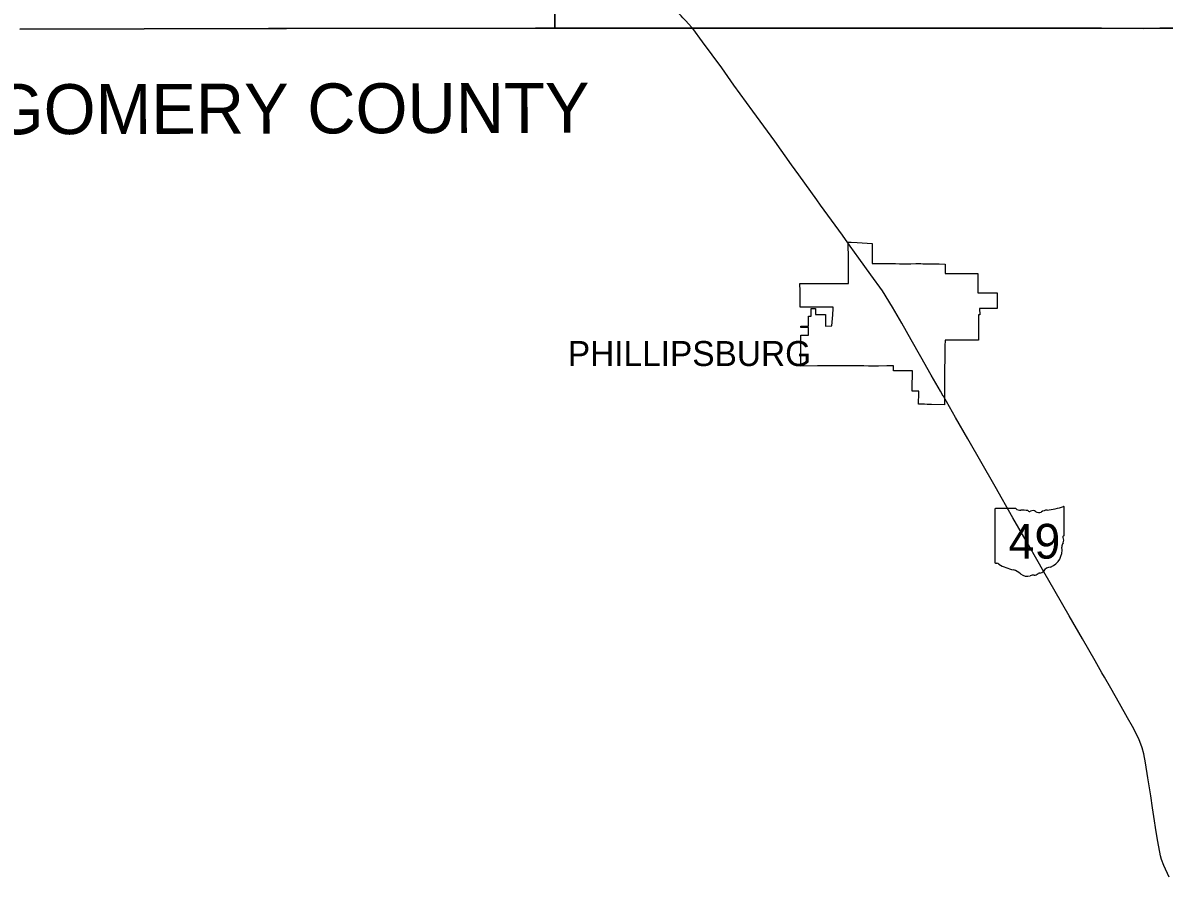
# Model space of a CAD drawing. Extents: x 0 to 34, y 0 to 22.
# Drawn here: x 4.0908 to 4.4592, y 15.8537 to 16.1285 of the extents above; entities that cross this region are included whole.
import ezdxf

# ---------------------------------------------------------------- set-up
doc = ezdxf.new("R2010")
doc.units = 0
for name, color, linetype in [('GM_X_Corporation', 7, 'Continuous'), ('GM_X_Corporation_Text', 7, 'Continuous'), ('GM_X_County', 7, 'Continuous'), ('GM_X_County_Text', 7, 'Continuous'), ('GM_X_State_Location', 7, 'Continuous'), ('GM_X_State_Route', 7, 'Continuous'), ('GM_X_State_Shield', 7, 'Continuous')]:
    doc.layers.add(name, color=color, linetype=linetype)

msp = doc.modelspace()

# ---------------------------------------------------------------- linework, layer by layer
at = {"layer": 'GM_X_Corporation'}
msp.add_lwpolyline([(4.341085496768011, 16.018143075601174), (4.341093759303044, 16.022683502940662), (4.3411005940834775, 16.026440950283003), (4.3411030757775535, 16.027804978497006), (4.34110357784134, 16.02808085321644), (4.343506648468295, 16.028083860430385), (4.3435106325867, 16.029144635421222), (4.343512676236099, 16.029687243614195), (4.343514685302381, 16.030490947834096), (4.341103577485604, 16.030491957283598), (4.34110357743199, 16.03099426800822), (4.34351468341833, 16.030994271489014), (4.343514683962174, 16.03113391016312), (4.343520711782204, 16.031801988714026), (4.343524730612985, 16.032605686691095), (4.343530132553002, 16.03347004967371), (4.343534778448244, 16.03421309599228), (4.344344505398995, 16.034214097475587), (4.344344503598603, 16.03662520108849), (4.345009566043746, 16.036626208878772), (4.345807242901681, 16.0366282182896), (4.3458190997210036, 16.03536338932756), (4.345825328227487, 16.03469933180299), (4.347750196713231, 16.034703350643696), (4.3486120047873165, 16.034704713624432), (4.3490220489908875, 16.03470536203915), (4.348983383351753, 16.031611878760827), (4.348975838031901, 16.031008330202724), (4.3510935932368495, 16.031036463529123), (4.351333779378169, 16.03457889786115), (4.351473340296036, 16.036637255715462), (4.351502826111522, 16.037079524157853), (4.351505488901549, 16.03711948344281), (4.34888066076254, 16.037116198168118), (4.348475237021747, 16.037115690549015), (4.348292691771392, 16.037115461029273), (4.340862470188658, 16.03710240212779), (4.340862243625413, 16.037120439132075), (4.34085644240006, 16.03758462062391), (4.340848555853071, 16.03826281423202), (4.340832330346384, 16.039658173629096), (4.340830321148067, 16.039851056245), (4.3408042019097, 16.042197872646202), (4.340776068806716, 16.044673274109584), (4.342391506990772, 16.04467126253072), (4.34404110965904, 16.044669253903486), (4.344065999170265, 16.044669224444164), (4.344866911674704, 16.044668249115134), (4.345188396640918, 16.044668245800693), (4.34596195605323, 16.044664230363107), (4.346735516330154, 16.044661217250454), (4.347509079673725, 16.04465720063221), (4.3482826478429, 16.0446541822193), (4.348472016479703, 16.04465477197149), (4.348604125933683, 16.044654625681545), (4.349488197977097, 16.04465619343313), (4.350372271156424, 16.044658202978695), (4.351256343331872, 16.044659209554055), (4.3521404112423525, 16.044660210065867), (4.352461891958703, 16.04466020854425), (4.353112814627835, 16.044660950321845), (4.353345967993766, 16.044661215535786), (4.354230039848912, 16.044662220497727), (4.354422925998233, 16.044663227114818), (4.355306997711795, 16.044664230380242), (4.3561910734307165, 16.044665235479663), (4.356351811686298, 16.044665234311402), (4.356383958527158, 16.04466523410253), (4.356380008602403, 16.04602670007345), (4.356377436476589, 16.046453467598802), (4.356376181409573, 16.046798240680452), (4.356372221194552, 16.04788323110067), (4.356364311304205, 16.050052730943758), (4.356362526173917, 16.050541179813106), (4.356355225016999, 16.052544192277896), (4.356353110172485, 16.053123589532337), (4.356352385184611, 16.053322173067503), (4.356351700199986, 16.05350920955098), (4.356351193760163, 16.053649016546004), (4.356340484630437, 16.056584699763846), (4.35633999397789, 16.056719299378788), (4.356336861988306, 16.057578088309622), (4.356335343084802, 16.05799540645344), (4.356406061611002, 16.05799161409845), (4.356743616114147, 16.057973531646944), (4.357298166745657, 16.057944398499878), (4.359186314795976, 16.057844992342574), (4.364015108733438, 16.057590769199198), (4.36402716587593, 16.05599943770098), (4.364033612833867, 16.055087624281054), (4.364041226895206, 16.05401128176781), (4.36404926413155, 16.052821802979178), (4.364050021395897, 16.052727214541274), (4.364057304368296, 16.05181717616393), (4.36405784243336, 16.05173083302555), (4.364061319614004, 16.051174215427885), (4.364061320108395, 16.051125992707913), (4.368284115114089, 16.051093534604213), (4.368354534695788, 16.05109299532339), (4.369700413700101, 16.051082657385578), (4.371469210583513, 16.0510690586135), (4.372819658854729, 16.0510586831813), (4.372903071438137, 16.051058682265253), (4.3730125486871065, 16.051058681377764), (4.376146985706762, 16.05106370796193), (4.376492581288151, 16.051064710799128), (4.378007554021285, 16.051066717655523), (4.378852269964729, 16.051067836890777), (4.379522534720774, 16.051068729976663), (4.379639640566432, 16.05106677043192), (4.380303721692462, 16.05105569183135), (4.383210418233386, 16.05100717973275), (4.384037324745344, 16.050993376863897), (4.38560227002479, 16.050967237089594), (4.387404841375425, 16.050937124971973), (4.3875022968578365, 16.050935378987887), (4.387517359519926, 16.050935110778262), (4.387521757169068, 16.050111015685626), (4.387527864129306, 16.04896635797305), (4.387533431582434, 16.04792323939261), (4.387538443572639, 16.047923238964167), (4.387662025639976, 16.04792324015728), (4.3877544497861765, 16.04792323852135), (4.389323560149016, 16.04791833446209), (4.397898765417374, 16.047891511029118), (4.398033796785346, 16.047891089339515), (4.398033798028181, 16.047731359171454), (4.3980337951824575, 16.047088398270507), (4.398031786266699, 16.04467729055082), (4.398031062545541, 16.043810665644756), (4.398031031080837, 16.043775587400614), (4.398029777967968, 16.042266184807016), (4.398029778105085, 16.041704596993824), (4.400103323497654, 16.04169856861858), (4.400881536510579, 16.041696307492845), (4.402176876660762, 16.04169254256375), (4.404250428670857, 16.041685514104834), (4.404248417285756, 16.03757156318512), (4.404248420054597, 16.03719972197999), (4.4042484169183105, 16.03709064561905), (4.404248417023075, 16.036599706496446), (4.398590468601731, 16.036610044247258), (4.398646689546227, 16.034580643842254), (4.3981666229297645, 16.034581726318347), (4.39821006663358, 16.031006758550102), (4.398264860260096, 16.02649755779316), (4.396633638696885, 16.026486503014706), (4.3902337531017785, 16.026443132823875), (4.387443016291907, 16.026424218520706), (4.387424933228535, 16.024531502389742), (4.387407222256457, 16.023441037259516), (4.3873710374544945, 16.021212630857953), (4.387352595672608, 16.02007698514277), (4.3873385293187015, 16.019120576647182), (4.387328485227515, 16.018409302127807), (4.387318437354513, 16.01766989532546), (4.387307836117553, 16.01690628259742), (4.387306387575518, 16.016801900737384), (4.387292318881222, 16.015757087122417), (4.38724208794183, 16.0121926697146), (4.387240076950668, 16.008964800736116), (4.3872400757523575, 16.008242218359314), (4.387241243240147, 16.00792820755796), (4.387259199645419, 16.006969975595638), (4.387262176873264, 16.00681088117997), (4.387285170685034, 16.00567280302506), (4.38306218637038, 16.00577555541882), (4.382939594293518, 16.005778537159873), (4.382885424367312, 16.005779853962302), (4.382762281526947, 16.00578285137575), (4.381801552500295, 16.00580622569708), (4.381679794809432, 16.005809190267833), (4.380837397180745, 16.00582968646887), (4.3807150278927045, 16.005832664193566), (4.379873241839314, 16.005853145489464), (4.379750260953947, 16.005856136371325), (4.378909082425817, 16.00587660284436), (4.378998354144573, 16.009545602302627), (4.379005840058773, 16.00985324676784), (4.379006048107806, 16.009861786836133), (4.379009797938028, 16.010015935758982), (4.379009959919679, 16.01002247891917), (4.377136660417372, 16.01006805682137), (4.376842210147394, 16.01007522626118), (4.376853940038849, 16.010557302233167), (4.376858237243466, 16.010733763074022), (4.377001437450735, 16.016618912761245), (4.376893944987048, 16.016617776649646), (4.37090768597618, 16.01655443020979), (4.370867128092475, 16.016554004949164), (4.370902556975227, 16.018171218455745), (4.370872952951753, 16.01817103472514), (4.368700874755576, 16.01815766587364), (4.366069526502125, 16.01814147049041), (4.364045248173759, 16.018129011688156), (4.362861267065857, 16.018140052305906), (4.361328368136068, 16.018154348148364), (4.3598923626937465, 16.01816773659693), (4.3571813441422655, 16.018193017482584), (4.357042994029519, 16.018194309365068), (4.356730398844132, 16.018197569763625), (4.356560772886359, 16.01819933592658), (4.354372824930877, 16.018186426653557), (4.353117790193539, 16.01817902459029), (4.348897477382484, 16.01815412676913), (4.348872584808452, 16.01815408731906), (4.346390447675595, 16.018150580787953)], close=True, dxfattribs=at)
at = {"layer": 'GM_X_County'}
for points in [[(4.261875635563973, 16.172098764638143), (4.2619589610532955, 16.126855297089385), (4.255771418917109, 16.126837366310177), (4.175676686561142, 16.126739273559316), (4.169824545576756, 16.126718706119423), (4.0898853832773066, 16.126467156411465)], [(4.460691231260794, 16.126814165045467), (4.456578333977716, 16.126806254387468), (4.451413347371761, 16.12677091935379), (4.437754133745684, 16.12682840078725), (4.433573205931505, 16.126836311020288), (4.43311229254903, 16.12683736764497), (4.429581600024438, 16.126838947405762), (4.419877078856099, 16.126838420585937), (4.410460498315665, 16.12684316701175), (4.410278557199, 16.126843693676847), (4.403633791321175, 16.1268189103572), (4.392137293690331, 16.126798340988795), (4.38380497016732, 16.12683842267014), (4.378373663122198, 16.126861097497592), (4.372256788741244, 16.12681679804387), (4.366508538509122, 16.126817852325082), (4.359810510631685, 16.126798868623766), (4.353482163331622, 16.126805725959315), (4.343777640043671, 16.126827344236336), (4.326637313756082, 16.126809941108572), (4.315245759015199, 16.126824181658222), (4.306333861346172, 16.126805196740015), (4.306256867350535, 16.12680572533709), (4.301271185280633, 16.126822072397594), (4.296259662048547, 16.126832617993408), (4.290617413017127, 16.12685002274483), (4.283602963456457, 16.126862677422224), (4.275322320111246, 16.126871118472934), (4.2675041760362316, 16.126875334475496), (4.264669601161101, 16.126876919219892), (4.2619589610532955, 16.126855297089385), (4.261875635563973, 16.172098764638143)], [(4.0898853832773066, 16.126467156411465), (4.169824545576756, 16.126718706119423), (4.175676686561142, 16.126739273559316), (4.255771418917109, 16.126837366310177), (4.2619589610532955, 16.126855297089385), (4.264669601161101, 16.126876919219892), (4.2675041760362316, 16.126875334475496), (4.275322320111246, 16.126871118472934), (4.283602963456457, 16.126862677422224), (4.290617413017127, 16.12685002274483), (4.296259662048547, 16.126832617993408), (4.301271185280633, 16.126822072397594), (4.306256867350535, 16.12680572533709), (4.306333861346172, 16.126805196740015), (4.315245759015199, 16.126824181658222), (4.326637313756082, 16.126809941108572), (4.343777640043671, 16.126827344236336), (4.353482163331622, 16.126805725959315), (4.359810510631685, 16.126798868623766), (4.366508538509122, 16.126817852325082), (4.372256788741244, 16.12681679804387), (4.378373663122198, 16.126861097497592), (4.38380497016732, 16.12683842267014), (4.392137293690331, 16.126798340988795), (4.403633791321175, 16.1268189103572), (4.410278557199, 16.126843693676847), (4.410460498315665, 16.12684316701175), (4.419877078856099, 16.126838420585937), (4.429581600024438, 16.126838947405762), (4.43311229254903, 16.12683736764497), (4.433573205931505, 16.126836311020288), (4.437754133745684, 16.12682840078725), (4.451413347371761, 16.12677091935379), (4.456578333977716, 16.126806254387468), (4.460691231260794, 16.126814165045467)]]:
    msp.add_lwpolyline(points, dxfattribs=at)
at = {"layer": 'GM_X_State_Route'}
for points in [[(4.306276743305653, 16.126760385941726), (4.30603942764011, 16.127014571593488), (4.303954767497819, 16.129246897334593), (4.3030972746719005, 16.130170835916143), (4.302554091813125, 16.130756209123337), (4.29701256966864, 16.136404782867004), (4.292661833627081, 16.14085466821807), (4.28246211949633, 16.151241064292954), (4.27769740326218, 16.156098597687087), (4.269736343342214, 16.164174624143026), (4.261895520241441, 16.172053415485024)], [(4.3569895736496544, 16.056661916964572), (4.354463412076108, 16.060187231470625), (4.347398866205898, 16.06987329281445), (4.346260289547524, 16.071560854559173), (4.340387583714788, 16.079640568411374), (4.338118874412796, 16.08287382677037), (4.33267491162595, 16.090435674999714), (4.325663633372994, 16.100148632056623), (4.319558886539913, 16.108538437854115), (4.315606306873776, 16.11406255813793), (4.309489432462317, 16.12247609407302), (4.306276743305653, 16.126760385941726)], [(4.37057590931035, 16.037097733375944), (4.367363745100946, 16.042293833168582), (4.363604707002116, 16.04743614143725), (4.359763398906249, 16.052790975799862), (4.3569895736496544, 16.056661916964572)], [(4.386885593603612, 16.0084788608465), (4.385979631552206, 16.01002243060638), (4.383033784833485, 16.015243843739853), (4.379699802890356, 16.02109440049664), (4.376560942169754, 16.0265794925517), (4.373504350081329, 16.03193802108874), (4.37057590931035, 16.037097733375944)], [(4.459494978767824, 15.853718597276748), (4.45781691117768, 15.857410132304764), (4.457125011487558, 15.859356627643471), (4.456763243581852, 15.860572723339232), (4.456516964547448, 15.861704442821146), (4.455769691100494, 15.86574456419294), (4.4551431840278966, 15.869670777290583), (4.45482676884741, 15.87182030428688), (4.454216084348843, 15.875965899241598), (4.453666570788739, 15.879873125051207), (4.452726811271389, 15.885600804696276), (4.451887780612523, 15.89051160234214), (4.451350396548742, 15.893353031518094), (4.450825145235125, 15.895355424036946), (4.450159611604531, 15.897340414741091), (4.449720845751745, 15.898400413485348), (4.44776697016, 15.902216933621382), (4.446193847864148, 15.905009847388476), (4.443576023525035, 15.909618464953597), (4.440731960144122, 15.914517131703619), (4.438732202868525, 15.917997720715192), (4.437937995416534, 15.919384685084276), (4.435711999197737, 15.923311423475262), (4.431646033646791, 15.930350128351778), (4.427422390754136, 15.93776431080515), (4.422835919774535, 15.945617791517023), (4.419255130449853, 15.951939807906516), (4.416967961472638, 15.955845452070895), (4.414289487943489, 15.96060753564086), (4.409311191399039, 15.969344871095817), (4.403538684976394, 15.979423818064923), (4.394827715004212, 15.994669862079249), (4.390819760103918, 16.001584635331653), (4.386926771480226, 16.00840869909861), (4.386885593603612, 16.0084788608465)]]:
    msp.add_lwpolyline(points, dxfattribs=at)
at = {"layer": 'GM_X_State_Shield'}
for p, q in [((4.410206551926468, 15.97225459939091), (4.403653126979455, 15.97225459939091)), ((4.425810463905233, 15.963790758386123), (4.425810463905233, 15.972675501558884)), ((4.403432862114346, 15.971962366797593), (4.403432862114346, 15.954977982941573)), ((4.4258082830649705, 15.963792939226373), (4.425810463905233, 15.963790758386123))]:
    msp.add_line(p, q, dxfattribs=at)
for centre, radius, start, end in [((4.4036891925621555, 15.971998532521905), 0.0002592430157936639, 98.1301027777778, 188.13010277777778), ((4.411767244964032, 15.97422631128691), 0.0025145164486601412, 231.61950555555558, 271.11188333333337), ((4.417839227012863, 15.995410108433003), 0.02373123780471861, 275.8444694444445, 288.9064527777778), ((4.425562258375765, 15.972712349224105), 0.000249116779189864, 351.8620861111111, 97.738), ((4.412600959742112, 15.962719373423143), 0.009027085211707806, 80.48669166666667, 94.98826944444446), ((4.414650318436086, 15.972086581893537), 0.0007254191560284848, 219.79206111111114, 297.1023694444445), ((4.415715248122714, 15.970123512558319), 0.0015082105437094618, 54.466683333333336, 119.14113055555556), ((4.417661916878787, 15.972816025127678), 0.0018143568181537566, 233.85620555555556, 294.82819166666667), ((4.420866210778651, 15.967067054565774), 0.004774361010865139, 97.34618055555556, 120.7688527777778), ((4.426703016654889, 15.960072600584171), 0.001683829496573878, 136.80649722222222, 186.92959444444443), ((4.425752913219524, 15.963138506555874), 0.00038552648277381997, 107.94398333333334, 210.33696666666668), ((4.423300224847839, 15.962015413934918), 0.002314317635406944, 340.0329638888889, 23.649566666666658), ((4.425544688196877, 15.96375643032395), 0.0002666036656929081, 289.6038111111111, 7.734130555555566), ((4.419168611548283, 15.958942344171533), 0.005935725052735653, 292.3088861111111, 8.985838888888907), ((4.403691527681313, 15.954940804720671), 0.00026154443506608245, 171.9583861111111, 258.30661388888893), ((4.403731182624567, 15.956678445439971), 0.0019959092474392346, 267.33899444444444, 280.6038555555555), ((4.40413953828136, 15.95399811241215), 0.000719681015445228, 29.748380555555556, 93.27174722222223), ((4.413225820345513, 15.969257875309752), 0.017137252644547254, 240.41292222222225, 257.1985), ((4.408116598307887, 15.947347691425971), 0.0053619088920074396, 47.184155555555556, 75.83597222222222), ((4.413915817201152, 15.953913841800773), 0.003402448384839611, 230.70037222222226, 286.29183611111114), ((4.415881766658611, 15.94804165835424), 0.0027957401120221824, 85.69512222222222, 111.20994722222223), ((4.416130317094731, 15.95264193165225), 0.0018128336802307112, 268.7770194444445, 315.54927222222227), ((4.417770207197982, 15.950997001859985), 0.0005103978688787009, 65.75173055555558, 132.64842222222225), ((4.417552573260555, 15.953331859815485), 0.0019176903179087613, 282.8731916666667, 323.27711111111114), ((4.421671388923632, 15.950209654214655), 0.0032508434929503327, 94.40312222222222, 142.57675)]:
    msp.add_arc(centre, radius, start, end, dxfattribs=at)

# ---------------------------------------------------------------- texts
at = {"layer": 'GM_X_Corporation_Text'}
msp.add_text('PHILLIPSBURG', height=0.008037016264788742, rotation=1.0000000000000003e-05, dxfattribs=at).set_placement((4.266133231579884, 16.018140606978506))
at = {"layer": 'GM_X_County_Text'}
msp.add_text('MONTGOMERY COUNTY', height=0.016074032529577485, rotation=0.15846799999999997, dxfattribs=at).set_placement((4.017539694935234, 16.092492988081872))
at = {"layer": 'GM_X_State_Location'}
msp.add_text('49', height=1.6074032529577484e-05, rotation=1.0000000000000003e-05, dxfattribs=at).set_placement((4.410321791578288, 15.9611715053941))
for s, p in [('s', (4.414369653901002, 15.962341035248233)), ('r', (4.414368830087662, 15.962341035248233))]:
    msp.add_text(s, height=1.6074032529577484e-05, dxfattribs=at).set_placement(p)
at = {"layer": 'GM_X_State_Shield'}
msp.add_text('49', height=0.011189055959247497, dxfattribs=at).set_placement((4.40789827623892, 15.95617567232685))

doc.saveas('drawing.dxf')
